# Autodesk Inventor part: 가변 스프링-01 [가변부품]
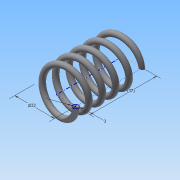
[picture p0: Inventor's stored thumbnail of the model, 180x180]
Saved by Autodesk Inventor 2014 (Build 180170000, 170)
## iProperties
Created: 2015-09
Part Number: 가변 스프링-01 [가변부품]
Material: 강철, 탄소
Document SubType Name: Modeling
Designer: study
Density: 1 g/cm^3
Appearance: 반연마
Author: study
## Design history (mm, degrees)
sketch "스케치1"
  geometry: L1 (0, 0)-(11, 0); L2 (11, 0)-(11, 40.761); L3 (11, 40.761)-(0, 40.761); L4 (0, 40.761)-(0, 0); C1 r 1.5 at (11, 0)
  constraints: 8 end point, 2 parallel, 1 centre point, 1 coincident, 1 horizontal, 1 perpendicular
  dimensions: "d0" = 22 diameter of L2 L4; "d1" = 3 diameter of C1; "d2" = 40.7612 distance between parallel lines of L3 L1 (derived)
feature "코일1" sketch "스케치1" pitch "d3" = 10; turns "d5" = 5; dims "d4" = 40.7612 (= d2), "d6" = 0, angle "d7" = 90 deg, angle "d8" = 90 deg, "d9" = 0, "d10" = 0
node "작업 평면1"
sketch "스케치2"
  geometry: L1 (-12.5, 0)-(-9.5, 0) reference; 1 further point
  constraints: 1 horizontal alignment
extrude "돌출1" cut sketch "스케치2" stored distance "d12" = 10; taper "d13" = 0 deg
node "작업 평면2"
sketch "스케치3"
  geometry: L1 (-9.5, 0)-(-12.5, 0) reference; L2 (-9.5, 0)-(-12.5, 0) reference; 1 further point
  constraints: 2 horizontal alignment
extrude "돌출2" cut sketch "스케치3" stored distance "d15" = 10; taper "d16" = 0 deg
node "솔리드1"
node "절단 모서리 투영1"
node "절단 모서리 투영2"
node "절단 모서리 투영3"
other parameters: "d11" = 0, "d14" = 40.7612 (= d2)
